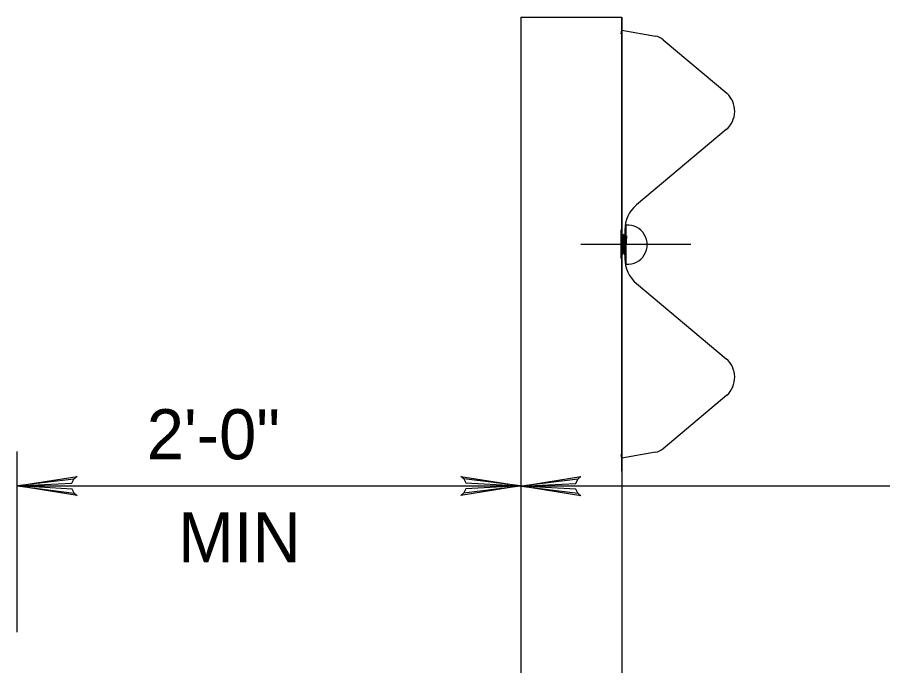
# Model space of a CAD drawing. Extents: x 637628 to 640188, y 298266 to 300751.
# Drawn here: x 638075.8 to 638127.6, y 299020.4 to 299059.3 of the extents above; entities that cross this region are included whole.
import ezdxf

# ---------------------------------------------------------------- set-up
doc = ezdxf.new("R2010")
doc.units = 0
doc.layers.add('2', color=7, linetype='Continuous')
doc.layers.add('3', color=7, linetype='Continuous')

msp = doc.modelspace()

# ---------------------------------------------------------------- linework, layer by layer
at = {"layer": '2'}
for p, q in [((638105.949, 299059.25), (638111.99, 299059.25)), ((638105.949, 299059.25), (638105.949, 298979.219)), ((638105.949, 299059.25), (638111.99, 299059.25)), ((638105.949, 299059.25), (638105.949, 298979.219)), ((638111.99, 299032.05), (638111.99, 299059.25)), ((638111.99, 299059.25), (638111.99, 298979.219)), ((638111.99, 299032.05), (638111.99, 299059.25)), ((638111.99, 299059.25), (638111.99, 298979.219)), ((638111.955, 299058.267), (638111.99, 299058.484)), ((638111.99, 299058.484), (638114.011, 299058.123)), ((638114.48, 299057.905), (638118.295, 299054.705)), ((638118.249, 299052.517), (638112.878, 299048.007)), ((638112.257, 299044.45), (638112.257, 299046.794)), ((638111.955, 299045.65), (638111.955, 299046.502)), ((638111.955, 299046.194), (638111.98, 299046.155)), ((638111.955, 299045.725), (638111.98, 299046.155)), ((638111.955, 299045.723), (638111.98, 299046.155)), ((638111.98, 299045.517), (638112.017, 299046.155)), ((638112.009, 299045.042), (638112.067, 299046.238)), ((638112.017, 299046.155), (638112.067, 299046.238)), ((638112.028, 299045.042), (638112.088, 299046.238)), ((638112.088, 299046.238), (638112.067, 299046.238)), ((638112.08, 299045.125), (638112.138, 299046.155)), ((638112.08, 299045.125), (638112.138, 299046.155)), ((638112.088, 299046.238), (638112.138, 299046.155)), ((638112.138, 299045.517), (638112.174, 299046.155)), ((638112.165, 299045.042), (638112.226, 299046.238)), ((638112.174, 299046.155), (638112.226, 299046.238)), ((638112.176, 299046.502), (638112.176, 299045.65)), ((638112.186, 299045.042), (638112.245, 299046.238)), ((638112.245, 299046.238), (638112.226, 299046.238)), ((638112.236, 299045.125), (638112.297, 299046.155)), ((638109.547, 299045.65), (638116.126, 299045.65)), ((638111.955, 299044.794), (638111.955, 299045.65)), ((638112.176, 299045.65), (638112.176, 299044.794)), ((638111.957, 299045.125), (638111.98, 299045.517)), ((638111.957, 299045.125), (638111.98, 299045.088)), ((638111.98, 299045.088), (638112.009, 299045.042)), ((638112.028, 299045.042), (638112.08, 299045.125)), ((638112.115, 299045.125), (638112.138, 299045.517)), ((638112.115, 299045.125), (638112.138, 299045.088)), ((638112.138, 299045.088), (638112.165, 299045.042)), ((638112.878, 299043.294), (638118.249, 299038.784)), ((638118.295, 299036.594), (638114.48, 299033.394)), ((638075.776, 299022.398), (638075.776, 299033.216)), ((638114.011, 299033.175), (638111.99, 299032.817)), ((638111.99, 299032.817), (638111.955, 299033.036)), ((638075.776, 299031.157), (638105.672, 299031.157)), ((638106.415, 299031.157), (638187.549, 299031.157)), ((638111.99, 299021.59), (638111.99, 299021.59)), ((638111.99, 299021.59), (638111.99, 299021.309)), ((638111.99, 299021.59), (638111.99, 299021.59)), ((638111.99, 299021.59), (638111.99, 299021.309))]:
    msp.add_line(p, q, dxfattribs=at)
for points in [[(638112.017, 299046.155), (638111.98, 299046.155)], [(638112.174, 299046.155), (638112.138, 299046.155)], [(638111.957, 299045.125), (638111.955, 299045.125)], [(638112.028, 299045.042), (638112.009, 299045.042)], [(638112.115, 299045.125), (638112.08, 299045.125)], [(638112.186, 299045.042), (638112.165, 299045.042)], [(638079.182, 299030.727), (638079.055, 299030.975), (638075.776, 299031.157), (638079.182, 299030.727), (638079.355, 299030.579), (638075.776, 299031.157), (638079.051, 299031.317), (638079.172, 299031.563), (638075.776, 299031.157), (638079.355, 299031.725), (638079.172, 299031.563)], [(638102.528, 299031.584), (638102.655, 299031.338), (638105.932, 299031.157), (638102.528, 299031.584), (638102.353, 299031.734), (638105.932, 299031.157), (638102.657, 299030.994), (638102.536, 299030.75), (638105.932, 299031.157), (638102.353, 299030.588), (638102.536, 299030.75)], [(638109.365, 299030.723), (638109.238, 299030.969), (638105.961, 299031.15), (638109.365, 299030.723), (638109.54, 299030.573), (638105.961, 299031.15), (638109.236, 299031.313), (638109.357, 299031.557), (638105.961, 299031.15), (638109.54, 299031.719), (638109.357, 299031.557)]]:
    msp.add_lwpolyline(points, dxfattribs=at)
for centre, radius, start, end in [((638113.837, 299057.138), 1.003, 50, 79.9701), ((638117.282, 299053.632), 1.476, 310.9606, 46.6292), ((638114.137, 299046.504), 1.962, 130.0127, 180), ((638112.341, 299045.622), 1.175, 265.9015, 94.0985), ((638114.137, 299044.797), 1.962, 180, 229.9873), ((638117.282, 299037.669), 1.476, 313.3708, 49.0394), ((638113.837, 299034.164), 1.003, 280.0299, 310)]:
    msp.add_arc(centre, radius, start, end, dxfattribs=at)

# ---------------------------------------------------------------- texts
at = {"layer": '3'}
for s, p in [('2\'-0"', (638083.532, 299032.759)), ('MIN', (638085.411, 299026.584))]:
    msp.add_text(s, height=3, dxfattribs=at).set_placement(p)

doc.saveas('drawing.dxf')
